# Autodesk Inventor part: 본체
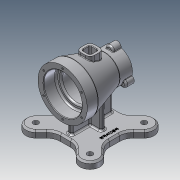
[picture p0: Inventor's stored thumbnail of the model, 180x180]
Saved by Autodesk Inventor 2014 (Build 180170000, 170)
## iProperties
Created: 2018-03
Part Number: 본체
Material: 알루미늄 6061
Document SubType Name: Modeling
Designer: NET
Mass: 1022.3 g
Surface Area: 859.007 cm^2
Volume: 377.231 cm^3
Density: 2.71 g/cm^3
Appearance: 알루미늄 - 평지
Author: NET
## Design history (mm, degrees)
sketch "스케치2"
  geometry: L1 (0, 0)-(100, 0); L2 (0, 0)-(0, 45); L3 (0, 45)-(20, 45); L4 (20, 45)-(77, 27.5); L5 (77, 27.5)-(100, 27.5); L6 (100, 27.5)-(100, 0)
  constraints: 12 end point, 3 perpendicular, 1 horizontal, 1 parallel
  dimensions: "d10" = 100 distance of L1.start L1.end; "d11" = 20 distance of L2.end L3.end; "d12" = 90 diameter of L3 L1; "d13" = 55 diameter of L5 L1; "d14" = 77 horizontal distance of L2.end L4.end
revolve "회전1" sketch "스케치2" stored, may be unused: angle "d15" = 90 deg
sketch "스케치3"
  geometry: L1 (0, 0)-(100, 0); L2 (0, 0)-(0, 35); L3 (0, 35)-(23, 35); L4 (23, 35)-(23, 26); L5 (23, 26)-(70, 26); L6 (70, 26)-(70, 20); L7 (70, 20)-(100, 20); L8 (100, 20)-(100, 0)
  constraints: 16 end point, 5 parallel, 2 perpendicular, 1 horizontal
  dimensions: "d16" = 100 distance of L1.start L1.end; "d17" = 23 distance of L2.end L3.end; "d18" = 47 distance of L4.end L5.end; "d19" = 70 diameter of L3 L1; "d20" = 52 diameter of L5 L1; "d21" = 40 diameter of L7 L1
revolve "회전2" sketch "스케치3" stored, may be unused: angle "d22" = 90 deg
chamfer "모따기1" distance "d23" = 1; stored, may be unused: second distance "d24" = 2, angle "d25" = 45 deg
fillet "모깎기1" dims "d26" = 3
fillet "모깎기2" dims "d27" = 3
chamfer "모따기2" distance "d28" = 1; stored, may be unused: second distance "d29" = 2, angle "d30" = 45 deg
fillet "모깎기3" dims "d31" = 3
node "작업 평면1"
sketch "스케치4"
  geometry: L1 (0, 0)-(-100, 0); L2 (-95, -45)-(-5, -45); L3 (-5, -45)-(-5, 45); L4 (-5, 45)-(-95, 45); L5 (-95, 45)-(-95, -45); L6 (-95, -45)-(-5, 45); L7 (-5, -45)-(-95, 45); 1 further point
  constraints: 14 end point, 3 midpoint, 2 horizontal, 2 parallel, 1 perpendicular
  dimensions: "d50" = 100 distance of L1.start L1.end; "d51" = 90 distance of L3.end L4.end; "d52" = 90 distance of L4.end L2.start
extrude "돌출2" join sketch "스케치4" distance "d53" = 12; taper "d54" = 0 deg
sketch "스케치5"
  geometry: L1 (0, 0)-(-100, 0); L2 (-50, 0)-(-0.503, -49.497); L3 (-5, -45)-(-5, 45) reference; L4 (-95, -45)-(-5, -45) reference; L5 (12.225, -36.77)-(-5, -19.544); L6 (-13.23, -62.225)-(-30.456, -45); L7 (-95, 45)-(-95, -45) reference; L8 (-5, 45)-(-95, 45) reference; L9 (-50, 0)-(-99.497, -49.497); L10 (-50, 0)-(-99.497, 49.497); L11 (-50, 0)-(-0.503, 49.497); L12 (-86.77, -62.225)-(-69.544, -45); L13 (-112.225, -36.77)-(-95.743, -20.287); L14 (12.225, 36.77)-(-5, 19.544); L15 (-13.23, 62.225)-(-30.456, 45); L16 (-86.77, 62.225)-(-69.544, 45); L17 (-112.225, 36.77)-(-95, 19.544); A1 r 70 centre (-50, 0) between (-0.503, -49.497) and (-99.497, -49.497); A2 r 18 centre (-0.503, -49.497) between (12.225, -36.77) and (-13.23, -62.225); A3 r 18 centre (-99.497, -49.497) between (-86.77, -62.225) and (-112.225, -36.77); A4 r 18 centre (-99.497, 49.497) between (-86.77, 62.225) and (-112.225, 36.77); A5 r 18 centre (-0.503, 49.497) between (12.225, 36.77) and (-13.23, 62.225)
  constraints: 26 end point, 12 point on circle, 8 tangent, 7 parallel, 6 point on line, 5 centre point, 4 coincident, 1 horizontal, 1 midpoint, 1 perpendicular
  dimensions: "d55" = 100 distance of L1.start L1.end; "d56" = 140 diameter of A1; "d57" = 45 deg angle of L1 L2; "d58" = 36 diameter of A2; "d61" = 45 deg angle of L1 L9; "d62" = 45 deg angle of L1 L10; "d63" = 45 deg angle of L1 L11; "d64" = 36 diameter of A3; "d65" = 36 diameter of A4; "d66" = 36 diameter of A5
extrude "돌출4" join sketch "스케치5" distance "d68" = 12; taper "d69" = 0 deg
node "작업 평면3"
fillet "모깎기4" dims "d71" = 25
fillet "모깎기5" dims "d72" = 25
fillet "모깎기6" dims "d73" = 25
sketch "스케치6"
  geometry: L1 (0, 0)-(-100, 0); C1 r 5 at (-0.503, -49.497); C2 r 5 at (-99.497, -49.497); C3 r 5 at (-0.503, 49.497); C4 r 5 at (-99.497, 49.497); A1 r 18 centre (-99.497, -49.497) between (-112.225, -36.77) and (-86.77, -62.225) reference; A2 r 18 centre (-0.503, -49.497) between (-13.23, -62.225) and (12.225, -36.77) reference; A3 r 18 centre (-0.503, 49.497) between (12.225, 36.77) and (-13.23, 62.225) reference; A4 r 18 centre (-99.497, 49.497) between (-86.77, 62.225) and (-112.225, 36.77) reference
  constraints: 4 centre point, 4 coincident, 2 end point, 1 horizontal
  dimensions: "d75" = 100 distance of L1.start L1.end; "d76" = 10 diameter of C1; "d77" = 10 diameter of C2; "d78" = 10 diameter of C3; "d79" = 10 diameter of C4
extrude "돌출5" cut sketch "스케치6" stored distance "d80" = 12; taper "d81" = 0 deg
sketch "스케치7"
  geometry: L1 (0, 0)-(-100, 0); L2 (-46, 24)-(-54, 24); L3 (-54, 24)-(-54, -24); L4 (-54, -24)-(-46, -24); L5 (-46, -24)-(-46, 24); L6 (-46, 24)-(-54, -24); L7 (-54, 24)-(-46, -24); L8 (-87, 4)-(-13, 4); L9 (-13, 4)-(-13, -4); L10 (-13, -4)-(-87, -4); L11 (-87, -4)-(-87, 4); L12 (-87, 4)-(-13, -4); L13 (-13, 4)-(-87, -4); 2 further points
  constraints: 26 end point, 6 midpoint, 4 parallel, 3 horizontal, 2 perpendicular
  dimensions: "d82" = 100 distance of L1.start L1.end; "d83" = 37 horizontal distance of L9.end point (-50, 0); "d84" = 24 vertical distance of L3.end point (-50, 0); "d85" = 8 distance of L8.end L9.end; "d86" = 8 distance of L3.end L4.end
extrude "돌출6" join sketch "스케치7" stored distance "d87" = 12; taper "d88" = 0 deg
fillet "모깎기8" dims "d89" = 3
fillet "모깎기9" dims "d90" = 3
fillet "모깎기10" dims "d91" = 3
node "작업 평면4"
sketch "스케치8"
  geometry: L1 (0, 0)-(-100, 0); L2 (-37.5, 12.5)-(-62.5, 12.5); L3 (-62.5, 12.5)-(-62.5, -12.5); L4 (-62.5, -12.5)-(-37.5, -12.5); L5 (-37.5, -12.5)-(-37.5, 12.5); L6 (-37.5, 12.5)-(-62.5, -12.5); L7 (-62.5, 12.5)-(-37.5, -12.5); 1 further point
  constraints: 14 end point, 3 midpoint, 2 horizontal, 2 parallel, 1 perpendicular
  dimensions: "d93" = 100 distance of L1.start L1.end; "d94" = 25 distance of L3.end L4.end; "d95" = 25 distance of L2.end L3.end
extrude "돌출7" join sketch "스케치8" stored distance "d96" = 12; taper "d97" = 0 deg
fillet "모깎기11" dims "d98" = 8
fillet "모깎기12" dims "d99" = 1
sketch "스케치9"
  geometry: L1 (0, 0)-(-100, 0); L2 (-42.5, 7.5)-(-57.5, 7.5); L3 (-57.5, 7.5)-(-57.5, -7.5); L4 (-57.5, -7.5)-(-42.5, -7.5); L5 (-42.5, -7.5)-(-42.5, 7.5); L6 (-42.5, 7.5)-(-57.5, -7.5); L7 (-57.5, 7.5)-(-42.5, -7.5); 1 further point
  constraints: 14 end point, 3 midpoint, 2 horizontal, 2 parallel, 1 perpendicular
  dimensions: "d100" = 100 distance of L1.start L1.end; "d101" = 15 distance of L3.end L4.end; "d102" = 15 distance of L4.end L2.start
extrude "돌출8" cut sketch "스케치9" stored distance "d103" = 12; taper "d104" = 0 deg
fillet "모깎기13" dims "d105" = 3
chamfer "모따기3" distance "d106" = 1; stored, may be unused: second distance "d107" = 2, angle "d108" = 45 deg
sketch "스케치11" dims "d118" = 80
  geometry: 3 further points
  constraints: 1 coincident, 1 horizontal alignment, 2 other
hole "구멍1" sketch "스케치11" at (-40, 0) diameter "d119" = 3.242; stored, may be unused: countersink angle "d123" = 90 deg, drill point angle "d125" = 118 deg; dims "d120" = 9, "d121" = 4, "d122" = 2, "d124" = 11
sketch "스케치13"
  geometry: L1 (0, 0)-(27.5, 0); L2 (0, 0)-(-19.093, 33.07); A1 r 27.5 centre (0, 0) between (27.5, 0) and (-13.75, 23.816); A2 r 7 centre (-13.75, 23.816) between (-7.292, 26.516) and (-19.317, 19.573); 1 further point
  constraints: 6 point on circle, 4 end point, 2 centre point, 1 coincident, 1 horizontal, 1 point on line
  dimensions: "d129" = 55 diameter of A1; "d130" = 120 deg angle of L2 L1; "d131" = 14 diameter of A2
extrude "돌출10" join sketch "스케치13" distance "d132" = 15; taper "d133" = 0 deg
fillet "모깎기16" dims "d137" = 3
fillet "모깎기17" dims "d138" = 1
sketch "스케치14"
  geometry: A1 r 7 centre (0, 0) between (-0.127, -6.999) and (-0.127, 6.999) reference; A2 r 7 centre (-41.25, 23.816) between (-35.125, 27.205) and (-47.248, 20.206) reference; A3 r 7 centre (-41.25, -23.816) between (-47.248, -20.206) and (-35.125, -27.205) reference; 2 further points
  constraints: 1 coincident
hole "구멍2" sketch "스케치14" at (0, 0) diameter "d139" = 3.242; stored, may be unused: countersink angle "d143" = 90 deg, drill point angle "d145" = 118 deg; dims "d140" = 9, "d141" = 4, "d142" = 2, "d144" = 11
sketch "스케치15"
  geometry: L1 (-86.77, -62.225)-(-76.866, -52.322) reference; L2 (-102.322, -26.866)-(-112.225, -36.77) reference; L3 (-95, 9.189)-(-95, -9.189) reference; L4 (-112.225, 36.77)-(-102.322, 26.866) reference; L5 (-76.866, 52.322)-(-86.77, 62.225) reference; L6 (-40.811, 45)-(-59.189, 45) reference; L7 (-23.134, 52.322)-(-13.23, 62.225) reference; L8 (12.225, 36.77)-(2.322, 26.866) reference; L9 (-5, -9.189)-(-5, 9.189) reference; L10 (2.322, -26.866)-(12.225, -36.77) reference; L11 (-13.23, -62.225)-(-23.134, -52.322) reference; L12 (-59.189, -45)-(-40.811, -45) reference; L13 (0, 0)-(-100, 0); C1 r 5 at (-0.503, 49.497) reference; C2 r 5 at (-0.503, -49.497) reference; C3 r 5 at (-99.497, -49.497) reference; C4 r 5 at (-99.497, 49.497) reference; A1 r 18 centre (-99.497, -49.497) between (-112.225, -36.77) and (-86.77, -62.225) reference; A2 r 25 centre (-120, -9.189) between (-102.322, -26.866) and (-95, -9.189) reference; A3 r 25 centre (-120, 9.189) between (-95, 9.189) and (-102.322, 26.866) reference; A4 r 18 centre (-99.497, 49.497) between (-86.77, 62.225) and (-112.225, 36.77) reference; A5 r 25 centre (-59.189, 70) between (-76.866, 52.322) and (-59.189, 45) reference; A6 r 25 centre (-40.811, 70) between (-40.811, 45) and (-23.134, 52.322) reference; A7 r 18 centre (-0.503, 49.497) between (12.225, 36.77) and (-13.23, 62.225) reference; A8 r 25 centre (20, 9.189) between (2.322, 26.866) and (-5, 9.189) reference; A9 r 25 centre (20, -9.189) between (-5, -9.189) and (2.322, -26.866) reference; A10 r 18 centre (-0.503, -49.497) between (-13.23, -62.225) and (12.225, -36.77) reference; A11 r 25 centre (-40.811, -70) between (-23.134, -52.322) and (-40.811, -45) reference; A12 r 25 centre (-59.189, -70) between (-59.189, -45) and (-76.866, -52.322) reference; 1 further point
  constraints: 2 end point, 1 parallel, 1 other
  dimensions: "d149" = 100 distance of L13.start L13.end; "d150" = 35 vertical distance of L13.start point (-50, 35); "d151" = 50 horizontal distance of L13.start point (-50, 35)
extrude "돌출11" join sketch "스케치15" distance "d152" = 0.5; taper "d153" = 0 deg
chamfer "모따기4" distance "d154" = 3; stored, may be unused: second distance "d155" = 2, angle "d156" = 45 deg
node "솔리드2"
mirror "대칭1"
pattern_circular "원형 패턴2" dims angle "d127" = 360 deg
pattern_circular "원형 패턴3" dims angle "d135" = 360 deg
pattern_circular "원형 패턴4" dims angle "d147" = 360 deg
node "투영된 루프1"
other parameters: "d32" = -82, "d92" = 45
